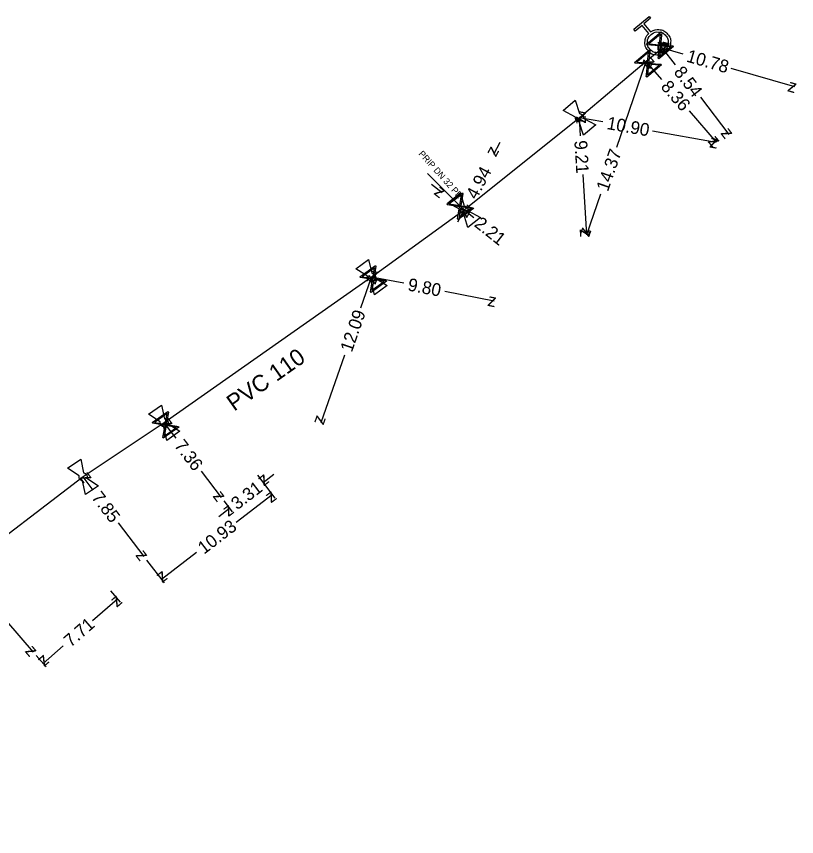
# Model space of a CAD drawing. Extents: x -638315 to -636370, y -1116147 to -1115110.
# Drawn here: x -637084.1 to -637022.9, y -1115705.8 to -1115641.5 of the extents above; entities that cross this region are included whole.
import ezdxf

# ---------------------------------------------------------------- set-up
doc = ezdxf.new("R2010")
doc.units = 0
for name, color, linetype in [('Default', 7, 'Continuous'), ('VP Hydrant', 7, 'Continuous'), ('VP Kótování', 7, 'Continuous'), ('VP Lomový bod', 7, 'Continuous'), ('VP Popis přípojky', 7, 'Continuous'), ('VP Přípojka', 7, 'Continuous'), ('VP Řad', 7, 'Continuous'), ('VP Řad - popis', 7, 'Continuous'), ('VP Šoupě', 7, 'Continuous')]:
    doc.layers.add(name, color=color, linetype=linetype)

msp = doc.modelspace()

# ---------------------------------------------------------------- linework, layer by layer
at = {"layer": 'Default'}
for points in [[(-637034.389, -1115642.738), (-637034.095, -1115642.53), (-637033.73, -1115642.563), (-637033.319, -1115642.601), (-637033.052, -1115642.92), (-637032.786, -1115643.238), (-637032.824, -1115643.65), (-637032.861, -1115644.062), (-637033.18, -1115644.329), (-637033.496, -1115644.593), (-637033.908, -1115644.557), (-637034.32, -1115644.521), (-637034.586, -1115644.204), (-637034.853, -1115643.885), (-637034.818, -1115643.473), (-637034.788, -1115643.107), (-637034.53, -1115642.856)], [(-637034.344, -1115642.937), (-637034.603, -1115643.154), (-637034.633, -1115643.488), (-637034.663, -1115643.823), (-637034.446, -1115644.082), (-637034.229, -1115644.341), (-637033.895, -1115644.371), (-637033.561, -1115644.4), (-637033.301, -1115644.183), (-637033.044, -1115643.968), (-637033.013, -1115643.633), (-637032.983, -1115643.298), (-637033.2, -1115643.039), (-637033.417, -1115642.78), (-637033.751, -1115642.75), (-637034.085, -1115642.72), (-637034.344, -1115642.937)], [(-637033.824, -1115644.003), (-637033.824, -1115643.909), (-637033.776, -1115643.819), (-637033.727, -1115643.729), (-637033.637, -1115643.679), (-637033.547, -1115643.628), (-637033.449, -1115643.628), (-637033.351, -1115643.628), (-637033.262, -1115643.677), (-637033.173, -1115643.727), (-637033.123, -1115643.816), (-637033.074, -1115643.906), (-637033.074, -1115644.003), (-637033.074, -1115644.1), (-637033.123, -1115644.19), (-637033.173, -1115644.279), (-637033.262, -1115644.329), (-637033.351, -1115644.378), (-637033.449, -1115644.378), (-637033.547, -1115644.378), (-637033.637, -1115644.328), (-637033.727, -1115644.277), (-637033.776, -1115644.188), (-637033.824, -1115644.098), (-637033.824, -1115644.003)], [(-637033.777, -1115644.003), (-637033.777, -1115644.086), (-637033.735, -1115644.165), (-637033.693, -1115644.243), (-637033.614, -1115644.287), (-637033.535, -1115644.331), (-637033.449, -1115644.331), (-637033.363, -1115644.331), (-637033.285, -1115644.288), (-637033.208, -1115644.245), (-637033.164, -1115644.167), (-637033.121, -1115644.088), (-637033.121, -1115644.003), (-637033.121, -1115643.918), (-637033.164, -1115643.839), (-637033.208, -1115643.761), (-637033.285, -1115643.718), (-637033.363, -1115643.675), (-637033.449, -1115643.675), (-637033.535, -1115643.675), (-637033.614, -1115643.719), (-637033.693, -1115643.764), (-637033.735, -1115643.842), (-637033.777, -1115643.921), (-637033.777, -1115644.003)], [(-637039.974, -1115649.773), (-637040.027, -1115649.772), (-637040.078, -1115649.753), (-637040.157, -1115649.723), (-637040.209, -1115649.661), (-637040.262, -1115649.598), (-637040.278, -1115649.513), (-637040.288, -1115649.461), (-637040.279, -1115649.408)], [(-637039.965, -1115649.146), (-637039.913, -1115649.147), (-637039.863, -1115649.165), (-637039.782, -1115649.197), (-637039.73, -1115649.26), (-637039.677, -1115649.322), (-637039.662, -1115649.405), (-637039.652, -1115649.459), (-637039.661, -1115649.511)], [(-637049.013, -1115657.017), (-637049.066, -1115657.016), (-637049.116, -1115656.995), (-637049.195, -1115656.964), (-637049.246, -1115656.9), (-637049.297, -1115656.837), (-637049.311, -1115656.751), (-637049.32, -1115656.699), (-637049.31, -1115656.647)], [(-637048.991, -1115656.391), (-637048.939, -1115656.393), (-637048.889, -1115656.412), (-637048.809, -1115656.445), (-637048.758, -1115656.509), (-637048.707, -1115656.573), (-637048.694, -1115656.656), (-637048.685, -1115656.71), (-637048.695, -1115656.762)], [(-637056.237, -1115661.639), (-637056.185, -1115661.644), (-637056.136, -1115661.665), (-637056.058, -1115661.702), (-637056.011, -1115661.769), (-637055.963, -1115661.835), (-637055.953, -1115661.919), (-637055.947, -1115661.973), (-637055.96, -1115662.024)], [(-637056.29, -1115662.263), (-637056.343, -1115662.259), (-637056.393, -1115662.236), (-637056.469, -1115662.201), (-637056.517, -1115662.135), (-637056.565, -1115662.068), (-637056.575, -1115661.982), (-637056.581, -1115661.929), (-637056.569, -1115661.878)], [(-637072.546, -1115673.678), (-637072.599, -1115673.673), (-637072.648, -1115673.649), (-637072.724, -1115673.613), (-637072.771, -1115673.546), (-637072.818, -1115673.479), (-637072.827, -1115673.393), (-637072.833, -1115673.34), (-637072.819, -1115673.289)], [(-637072.485, -1115673.054), (-637072.433, -1115673.06), (-637072.384, -1115673.082), (-637072.307, -1115673.12), (-637072.26, -1115673.187), (-637072.213, -1115673.254), (-637072.205, -1115673.338), (-637072.199, -1115673.392), (-637072.213, -1115673.443)], [(-637078.908, -1115677.92), (-637078.96, -1115677.914), (-637079.009, -1115677.89), (-637079.084, -1115677.852), (-637079.13, -1115677.784), (-637079.175, -1115677.716), (-637079.181, -1115677.629), (-637079.186, -1115677.576), (-637079.171, -1115677.526)], [(-637078.831, -1115677.298), (-637078.78, -1115677.305), (-637078.732, -1115677.329), (-637078.655, -1115677.369), (-637078.61, -1115677.437), (-637078.564, -1115677.505), (-637078.558, -1115677.589), (-637078.554, -1115677.643), (-637078.569, -1115677.694)]]:
    msp.add_open_spline(points, degree=3, dxfattribs=at)
at = {"layer": 'VP Hydrant'}
msp.add_lwpolyline([(-637034.53, -1115642.856), (-637035.056, -1115642.226), (-637035.585, -1115642.669), (-637035.703, -1115642.528), (-637034.505, -1115641.525), (-637034.387, -1115641.666), (-637034.915, -1115642.109), (-637034.389, -1115642.738)], dxfattribs=at)
at = {"layer": 'VP Kótování'}
for points in [[(-637032.435, -1115645.32), (-637033.449, -1115644.003)], [(-637031.836, -1115644.475), (-637033.449, -1115644.003)], [(-637037.039, -1115651.77), (-637034.72, -1115645.066)], [(-637033.494, -1115646.478), (-637034.72, -1115645.066)], [(-637028.085, -1115645.572), (-637023.1, -1115647.03)], [(-637030.478, -1115647.863), (-637028.24, -1115650.77)], [(-637031.37, -1115648.926), (-637029.24, -1115651.38)], [(-637038.127, -1115649.79), (-637039.97, -1115649.46)], [(-637039.885, -1115650.885), (-637039.97, -1115649.46)], [(-637034.225, -1115650.488), (-637029.24, -1115651.38)], [(-637046.199, -1115651.412), (-637046.69, -1115652.34)], [(-637039.704, -1115653.912), (-637039.42, -1115658.65)], [(-637051.552, -1115654.676), (-637050.73, -1115655.33)], [(-637038.317, -1115655.463), (-637039.42, -1115658.65)], [(-637049.493, -1115657.633), (-637049.002, -1115656.705)], [(-637048.242, -1115657.309), (-637049.002, -1115656.705)], [(-637057.107, -1115664.372), (-637056.264, -1115661.952)], [(-637053.723, -1115662.44), (-637056.264, -1115661.952)], [(-637050.518, -1115663.055), (-637046.64, -1115663.8)], [(-637058.392, -1115668.063), (-637060.24, -1115673.37)], [(-637071.588, -1115674.58), (-637072.516, -1115673.367)], [(-637069.62, -1115677.155), (-637068.048, -1115679.21)], [(-637078.08, -1115678.643), (-637078.87, -1115677.61)], [(-637065.207, -1115677.478), (-637063.836, -1115679.271)], [(-637065.207, -1115677.478), (-637064.551, -1115678.337)], [(-637063.929, -1115677.421), (-637064.763, -1115678.059)], [(-637066.873, -1115681.153), (-637064.049, -1115678.993)], [(-637067.835, -1115679.488), (-637067.179, -1115680.347)], [(-637068.225, -1115680.707), (-637067.391, -1115680.069)], [(-637076.13, -1115681.193), (-637074.104, -1115683.842)], [(-637069.978, -1115683.528), (-637072.733, -1115685.635)], [(-637073.891, -1115684.12), (-637072.52, -1115685.913)], [(-637076.721, -1115686.545), (-637075.953, -1115687.431)], [(-637078.143, -1115688.866), (-637076.182, -1115687.167)], [(-637084.864, -1115688.918), (-637082.776, -1115691.328)], [(-637080.436, -1115690.852), (-637082.008, -1115692.215)], [(-637082.547, -1115691.593), (-637081.779, -1115692.479)]]:
    msp.add_lwpolyline(points, dxfattribs=at)
at = {"layer": 'VP Lomový bod'}
for points in [[(-637041.251, -1115648.903), (-637040.292, -1115648.1), (-637039.965, -1115649.146)], [(-637040.279, -1115649.408), (-637041.251, -1115648.903)], [(-637039.661, -1115649.511), (-637038.688, -1115650.018), (-637039.647, -1115650.82), (-637039.974, -1115649.773)], [(-637050.272, -1115656.121), (-637049.297, -1115655.339), (-637048.991, -1115656.391)], [(-637049.31, -1115656.647), (-637050.272, -1115656.121)], [(-637048.695, -1115656.762), (-637047.732, -1115657.289), (-637048.707, -1115658.071), (-637049.013, -1115657.017)], [(-637057.503, -1115661.305), (-637056.489, -1115660.572), (-637056.237, -1115661.639)], [(-637056.569, -1115661.878), (-637057.503, -1115661.305)], [(-637055.96, -1115662.024), (-637055.025, -1115662.599), (-637056.038, -1115663.331), (-637056.29, -1115662.263)], [(-637073.745, -1115672.703), (-637072.723, -1115671.985), (-637072.485, -1115673.054)], [(-637072.819, -1115673.289), (-637073.745, -1115672.703)], [(-637072.213, -1115673.443), (-637071.286, -1115674.03), (-637072.309, -1115674.749), (-637072.546, -1115673.678)], [(-637080.084, -1115676.918), (-637079.044, -1115676.224), (-637078.831, -1115677.298)], [(-637079.171, -1115677.526), (-637080.084, -1115676.918)], [(-637078.569, -1115677.694), (-637077.656, -1115678.303), (-637078.695, -1115678.997), (-637078.908, -1115677.92)]]:
    msp.add_lwpolyline(points, dxfattribs=at)
at = {"layer": 'VP Přípojka'}
for points in [[(-637033.831, -1115643.544), (-637033.66, -1115643.79), (-637033.449, -1115644.003)], [(-637034.72, -1115645.066), (-637034.591, -1115645.22)], [(-637049.002, -1115656.705), (-637049.304, -1115656.398), (-637051.883, -1115653.839)], [(-637049.14, -1115656.56), (-637049.002, -1115656.705)], [(-637056.264, -1115661.952), (-637056.13, -1115662.1)], [(-637072.516, -1115673.367), (-637072.4, -1115673.53)]]:
    msp.add_lwpolyline(points, dxfattribs=at)
at = {"layer": 'VP Řad'}
msp.add_lwpolyline([(-637033.449, -1115644.003), (-637034.72, -1115645.066), (-637037.433, -1115647.337), (-637039.97, -1115649.46), (-637049.002, -1115656.705), (-637049.937, -1115657.383), (-637056.219, -1115661.919), (-637056.264, -1115661.952), (-637072.516, -1115673.367), (-637078.87, -1115677.61), (-637088.38, -1115684.86), (-637099.879, -1115697.112), (-637109.13, -1115705.79)], dxfattribs=at)
at = {"layer": 'VP Šoupě'}
for points in [[(-637032.597, -1115643.893), (-637033.747, -1115644.855), (-637033.79, -1115644.805), (-637033.774, -1115644.677), (-637033.701, -1115643.84), (-637034.668, -1115643.756), (-637034.71, -1115643.705), (-637033.56, -1115642.742), (-637033.517, -1115642.793), (-637033.605, -1115643.76), (-637032.769, -1115643.834), (-637032.639, -1115643.842), (-637032.597, -1115643.893)], [(-637034.533, -1115643.679), (-637033.693, -1115643.753), (-637033.62, -1115642.915), (-637034.533, -1115643.679)], [(-637033.535, -1115645.314), (-637034.685, -1115646.276), (-637034.728, -1115646.226), (-637034.712, -1115646.098), (-637034.639, -1115645.261), (-637035.606, -1115645.177), (-637035.648, -1115645.126), (-637034.498, -1115644.163), (-637034.455, -1115644.214), (-637034.543, -1115645.181), (-637033.707, -1115645.255), (-637033.577, -1115645.263), (-637033.535, -1115645.314)], [(-637035.471, -1115645.1), (-637034.631, -1115645.174), (-637034.558, -1115644.336), (-637035.471, -1115645.1)], [(-637032.778, -1115643.922), (-637033.613, -1115643.848), (-637033.686, -1115644.682), (-637032.778, -1115643.922)], [(-637033.716, -1115645.343), (-637034.551, -1115645.269), (-637034.624, -1115646.103), (-637033.716, -1115645.343)], [(-637048.257, -1115656.566), (-637049.473, -1115657.445), (-637049.511, -1115657.391), (-637049.487, -1115657.265), (-637049.354, -1115656.436), (-637050.312, -1115656.282), (-637050.351, -1115656.229), (-637049.135, -1115655.351), (-637049.097, -1115655.404), (-637049.253, -1115656.363), (-637048.424, -1115656.495), (-637048.295, -1115656.513), (-637048.257, -1115656.566)], [(-637050.173, -1115656.216), (-637049.34, -1115656.349), (-637049.207, -1115655.518), (-637050.173, -1115656.216)], [(-637048.439, -1115656.583), (-637049.267, -1115656.45), (-637049.399, -1115657.276), (-637048.439, -1115656.583)], [(-637055.083, -1115662.268), (-637056.299, -1115663.147), (-637056.337, -1115663.093), (-637056.313, -1115662.967), (-637056.18, -1115662.138), (-637057.138, -1115661.984), (-637057.177, -1115661.931), (-637055.961, -1115661.053), (-637055.923, -1115661.106), (-637056.079, -1115662.065), (-637055.25, -1115662.197), (-637055.121, -1115662.215), (-637055.083, -1115662.268)], [(-637056.999, -1115661.918), (-637056.166, -1115662.051), (-637056.033, -1115661.22), (-637056.999, -1115661.918)], [(-637055.265, -1115662.285), (-637056.093, -1115662.152), (-637056.225, -1115662.978), (-637055.265, -1115662.285)], [(-637071.355, -1115673.712), (-637072.583, -1115674.574), (-637072.621, -1115674.521), (-637072.595, -1115674.395), (-637072.451, -1115673.567), (-637073.407, -1115673.401), (-637073.445, -1115673.347), (-637072.218, -1115672.485), (-637072.18, -1115672.539), (-637072.349, -1115673.496), (-637071.521, -1115673.639), (-637071.393, -1115673.658), (-637071.355, -1115673.712)], [(-637073.266, -1115673.336), (-637072.436, -1115673.48), (-637072.292, -1115672.652), (-637073.266, -1115673.336)], [(-637071.538, -1115673.726), (-637072.364, -1115673.582), (-637072.507, -1115674.407), (-637071.538, -1115673.726)]]:
    msp.add_lwpolyline(points, dxfattribs=at)

# ---------------------------------------------------------------- texts
at = {"layer": 'VP Kótování'}
for s, rotation, p in [('z', 127.58785, (-637032.748, -1115644.094)), ('z', 163.69622, (-637032.829, -1115643.663)), ('10.78', 343.69624, (-637031.641, -1115645.053)), ('z', 70.91464, (-637034.411, -1115645.702)), ('z', 130.95512, (-637034.015, -1115645.116)), ('8.54', 307.58781, (-637032.618, -1115645.903)), ('8.36', 310.95514, (-637033.642, -1115647.071)), ('z', 343.6962, (-637023.72, -1115647.37)), ('z', 169.855, (-637039.39, -1115649.056)), ('z', 93.42495, (-637039.441, -1115649.929)), ('10.90', 349.85502, (-637037.871, -1115650.344)), ('z', 310.9551, (-637029.945, -1115651.33)), ('z', 307.58783, (-637028.941, -1115650.679)), ('9.21', 273.42491, (-637040.363, -1115651.264)), ('z', 349.85498, (-637029.82, -1115651.784)), ('z', 242.09124, (-637046.898, -1115651.664)), ('14.37', 70.91464, (-637037.73, -1115655.296)), ('4.94', 62.09126, (-637048.029, -1115655.937)), ('z', 321.49013, (-637051.433, -1115655.41)), ('z', 62.09126, (-637048.794, -1115657.381)), ('z', 141.49009, (-637048.299, -1115656.625)), ('2.21', 321.49011, (-637048.28, -1115657.919)), ('z', 273.42493, (-637039.949, -1115658.181)), ('z', 250.91462, (-637039.729, -1115658.014)), ('z', 70.80074, (-637055.956, -1115662.589)), ('z', 169.13038, (-637055.679, -1115661.555)), ('9.80', 349.1304, (-637053.474, -1115662.997)), ('z', 349.13036, (-637047.225, -1115664.197)), ('12.09', 70.80074, (-637057.805, -1115667.896)), ('z', 127.40427, (-637071.815, -1115673.46)), ('z', 250.80078, (-637060.548, -1115672.733)), ('7.36', 307.40429, (-637071.773, -1115675.162)), ('z', 127.40742, (-637078.169, -1115677.703)), ('z', 217.41023, (-637064.67, -1115677.358)), ('3.31', 37.41019, (-637066.788, -1115680.237)), ('7.85', 307.40738, (-637078.264, -1115679.225)), ('z', 307.40425, (-637068.749, -1115679.117)), ('z', 37.41076, (-637064.142, -1115679.694)), ('z', 37.41019, (-637067.485, -1115680.77)), ('10.93', 37.41076, (-637069.396, -1115683.712)), ('z', 307.4074, (-637074.805, -1115683.749)), ('z', 217.41074, (-637072.639, -1115684.934)), ('z', 40.90764, (-637076.232, -1115687.872)), ('7.71', 40.90764, (-637079.844, -1115691.001)), ('z', 310.90628, (-637083.481, -1115691.278)), ('z', 220.90762, (-637081.957, -1115691.509))]:
    msp.add_text(s, height=1, rotation=rotation, dxfattribs=at).set_placement(p)
at = {"layer": 'VP Popis přípojky'}
msp.add_text('PRIP DN 32 PE', height=0.5, rotation=311.89044, dxfattribs=at).set_placement((-637052.609, -1115652.316))
at = {"layer": 'VP Řad - popis'}
msp.add_text('PVC 110', height=1.3, rotation=35.08324, dxfattribs=at).set_placement((-637067.032, -1115672.506))

doc.saveas('drawing.dxf')
